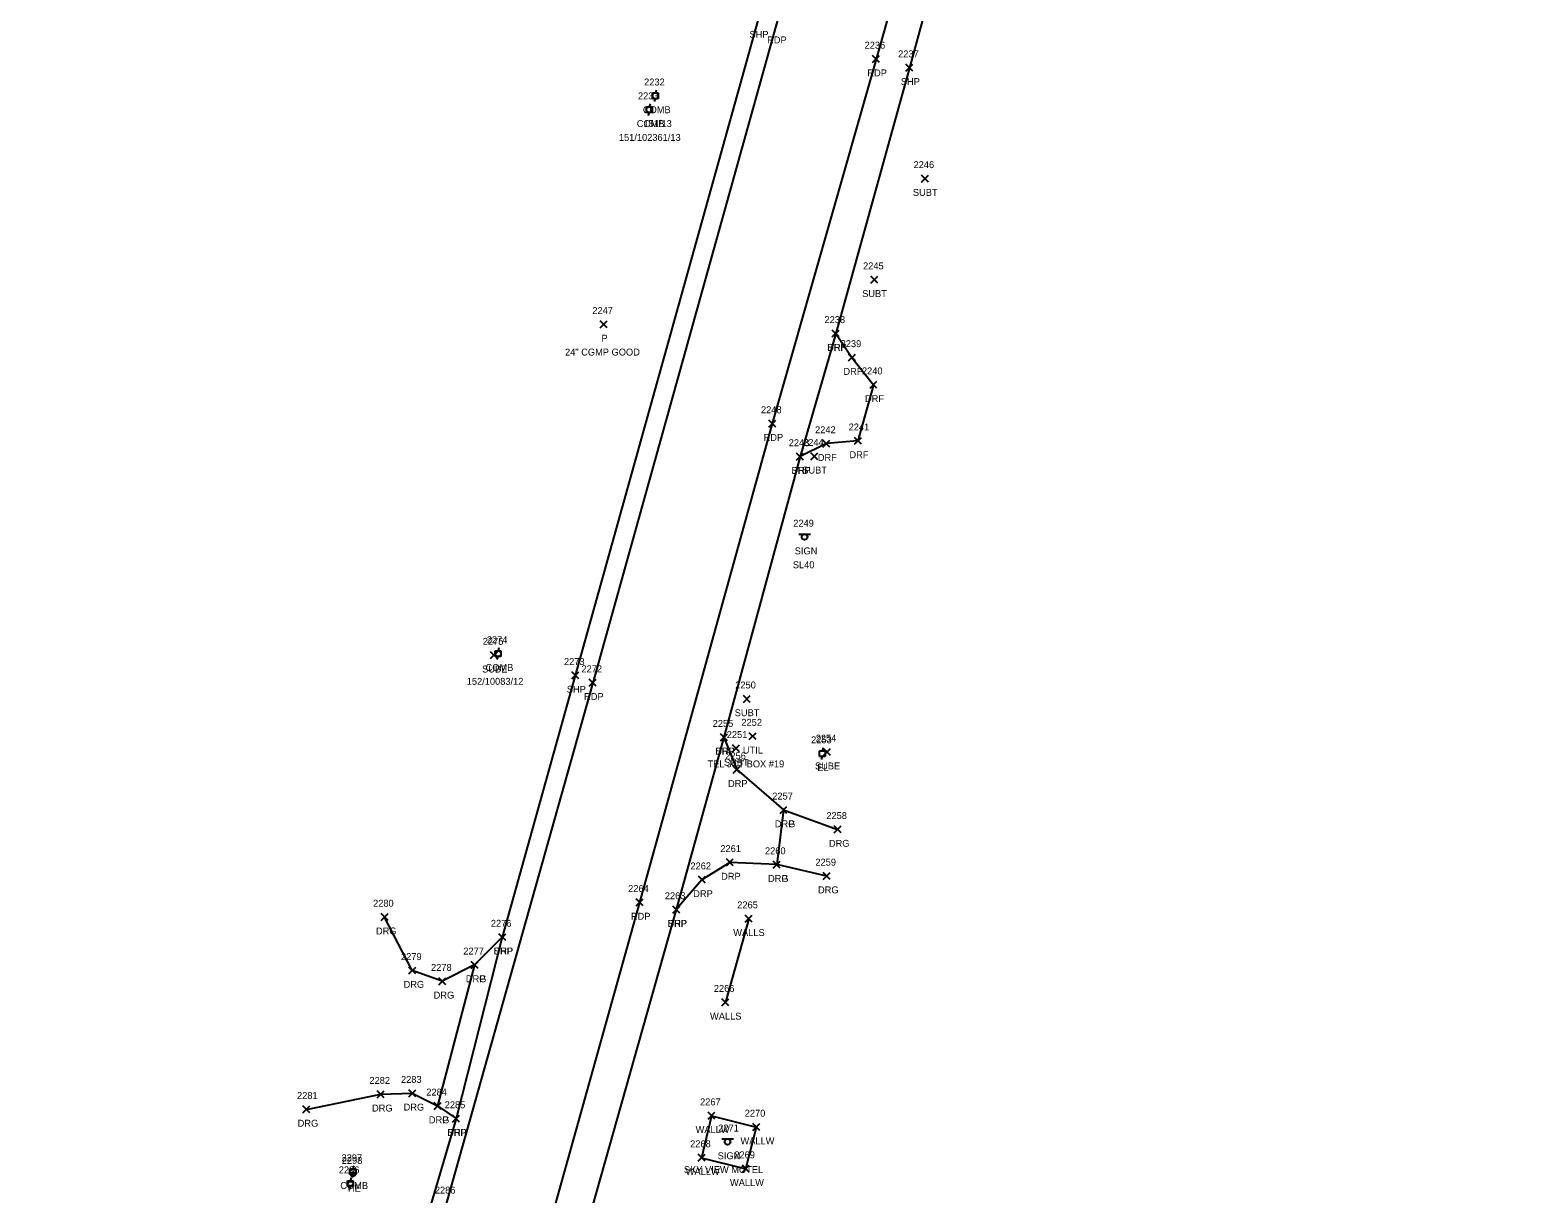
# Model space of a CAD drawing. Extents: x 1443071 to 1445292, y 614024 to 622563.
# Drawn here: x 1444319.1 to 1444754.4, y 621556.7 to 621892.6 of the extents above; entities that cross this region are included whole.
import ezdxf

# ---------------------------------------------------------------- set-up
doc = ezdxf.new("R2010")
doc.units = 0
for name, color, linetype in [('C_A', 7, 'Continuous'), ('C_I', 7, 'Continuous'), ('CBP', 7, 'Continuous'), ('D_A', 7, 'Continuous'), ('D_C', 7, 'Continuous'), ('D_I', 7, 'Continuous'), ('D_TIC', 7, 'Continuous'), ('L_A', 7, 'Continuous'), ('L_I', 7, 'Continuous'), ('L_TIC', 7, 'Continuous'), ('LW', 7, 'Continuous'), ('LWS', 7, 'Continuous'), ('P_A', 7, 'Continuous'), ('P_I', 7, 'Continuous'), ('P_TIC', 7, 'Continuous'), ('PET', 7, 'Continuous'), ('PSP', 7, 'Continuous'), ('R_A', 7, 'Continuous'), ('R_I', 7, 'Continuous'), ('R_TIC', 7, 'Continuous'), ('RDF', 7, 'Continuous'), ('RDG', 7, 'Continuous'), ('RDP', 7, 'Continuous'), ('S_A', 7, 'Continuous'), ('S_C', 7, 'Continuous'), ('S_I', 7, 'Continuous'), ('SSGN', 7, 'Continuous'), ('U_A', 7, 'Continuous'), ('U_C', 7, 'Continuous'), ('U_I', 7, 'Continuous'), ('U_TIC', 7, 'Continuous'), ('UDEFAULT', 7, 'Continuous'), ('UEPT', 7, 'Continuous'), ('UP', 7, 'Continuous')]:
    doc.layers.add(name, color=color, linetype=linetype)

msp = doc.modelspace()

# ---------------------------------------------------------------- linework, layer by layer
at = {"layer": 'CBP'}
for radius in [0.625, 0.0833]:
    msp.add_circle((1444412.36, 621562.38), radius, dxfattribs=at)
at = {"layer": 'D_TIC'}
for points in [[(1444483.71, 621806.69), (1444485.71, 621808.69)], [(1444485.71, 621806.69), (1444483.71, 621808.69)]]:
    msp.add_lwpolyline(points, dxfattribs=at)
at = {"layer": 'L_TIC'}
for points in [[(1444525.6, 621635.14), (1444527.6, 621637.14)], [(1444527.6, 621635.14), (1444525.6, 621637.14)], [(1444518.88, 621611.03), (1444520.88, 621613.03)], [(1444520.88, 621611.03), (1444518.88, 621613.03)], [(1444514.86, 621578.28), (1444516.86, 621580.28)], [(1444516.86, 621578.28), (1444514.86, 621580.28)], [(1444514.86, 621578.28), (1444516.86, 621580.28)], [(1444516.86, 621578.28), (1444514.86, 621580.28)], [(1444527.8, 621575.01), (1444529.8, 621577.01)], [(1444529.8, 621575.01), (1444527.8, 621577.01)], [(1444527.8, 621575.01), (1444529.8, 621577.01)], [(1444529.8, 621575.01), (1444527.8, 621577.01)], [(1444512, 621566.17), (1444514, 621568.17)], [(1444514, 621566.17), (1444512, 621568.17)], [(1444524.76, 621563), (1444526.76, 621565)], [(1444526.76, 621563), (1444524.76, 621565)]]:
    msp.add_lwpolyline(points, dxfattribs=at)
at = {"layer": 'LW'}
for points in [[(1444515.86, 621579.28), (1444513, 621567.17), (1444525.76, 621564), (1444528.8, 621576.01)], [(1444515.86, 621579.28), (1444528.8, 621576.01)]]:
    msp.add_lwpolyline(points, dxfattribs=at)
at = {"layer": 'LWS'}
msp.add_lwpolyline([(1444526.6, 621636.14), (1444519.88, 621612.03)], dxfattribs=at)
at = {"layer": 'P_TIC'}
for points in [[(1444562.37, 621883.27), (1444564.37, 621885.27)], [(1444564.37, 621883.27), (1444562.37, 621885.27)], [(1444571.99, 621880.76), (1444573.99, 621882.76)], [(1444573.99, 621880.76), (1444571.99, 621882.76)], [(1444550.74, 621804.05), (1444552.74, 621806.05)], [(1444552.74, 621804.05), (1444550.74, 621806.05)], [(1444532.4, 621778.05), (1444534.4, 621780.05)], [(1444534.4, 621778.05), (1444532.4, 621780.05)], [(1444540.41, 621768.53), (1444542.41, 621770.53)], [(1444542.41, 621768.53), (1444540.41, 621770.53)], [(1444475.53, 621705.36), (1444477.53, 621707.36)], [(1444477.53, 621705.36), (1444475.53, 621707.36)], [(1444480.57, 621703.27), (1444482.57, 621705.27)], [(1444482.57, 621703.27), (1444480.57, 621705.27)], [(1444518.46, 621687.51), (1444520.46, 621689.51)], [(1444520.46, 621687.51), (1444518.46, 621689.51)], [(1444494.09, 621639.86), (1444496.09, 621641.86)], [(1444496.09, 621639.86), (1444494.09, 621641.86)], [(1444504.68, 621637.77), (1444506.68, 621639.77)], [(1444506.68, 621637.77), (1444504.68, 621639.77)], [(1444454.46, 621629.82), (1444456.46, 621631.82)], [(1444456.46, 621629.82), (1444454.46, 621631.82)], [(1444441.09, 621577.45), (1444443.09, 621579.45)], [(1444443.09, 621577.45), (1444441.09, 621579.45)]]:
    msp.add_lwpolyline(points, dxfattribs=at)
at = {"layer": 'PET'}
for points in [[(1444754.44, 622544.13), (1444741.07, 622497.37), (1444724.21, 622436.63), (1444710.62, 622388.87), (1444697.45, 622342.15), (1444675, 622264.13), (1444650.85, 622183.92), (1444630.28, 622116), (1444610.88, 622049.25), (1444594.96, 621996.24), (1444563.37, 621884.27), (1444533.4, 621779.05), (1444495.09, 621640.86), (1444437.04, 621433.18), (1444409.83, 621332.84), (1444393.99, 621275.61), (1444360.23, 621155.32)], [(1444707.59, 622509.11), (1444700.19, 622484.07), (1444679.05, 622409.28), (1444655.77, 622327.83), (1444650.07, 622306.66), (1444636.13, 622255.68), (1444623.55, 622208.8), (1444606.26, 622146.53), (1444595.29, 622106.04), (1444582.56, 622060.23), (1444534.43, 621893.79), (1444481.57, 621704.27), (1444439.29, 621553.82), (1444408.11, 621445.28), (1444395.03, 621397.39), (1444367.96, 621301.44), (1444350.41, 621238.76), (1444319.14, 621126.97)]]:
    msp.add_lwpolyline(points, dxfattribs=at)
at = {"layer": 'PSP'}
for points in [[(1444703.05, 622509.58), (1444696.35, 622485.04), (1444679.96, 622426.95), (1444670.67, 622398.4), (1444651.65, 622328.99), (1444645.77, 622309.01), (1444600.31, 622147.99), (1444589.19, 622108.06), (1444575.49, 622063.15), (1444529.28, 621895.39), (1444476.53, 621706.36), (1444455.46, 621630.82), (1444442.09, 621578.45), (1444424.77, 621519.75), (1444412.09, 621475.26), (1444390.88, 621397.93), (1444363.76, 621301.82), (1444345.99, 621239.2), (1444324.65, 621163.68)], [(1444745.15, 622495.54), (1444738.65, 622472.69), (1444728.21, 622436.2), (1444714.89, 622387.13), (1444701.45, 622339.69), (1444679.77, 622260.17), (1444671.12, 622229.57), (1444657.52, 622182.26), (1444644.19, 622133.53), (1444626.95, 622072.43), (1444608.5, 622007.83), (1444599.1, 621977.5), (1444572.99, 621881.76), (1444551.74, 621805.05), (1444541.41, 621769.53), (1444519.46, 621688.51), (1444505.68, 621638.77), (1444452.32, 621450.13), (1444441.68, 621411.27), (1444418.22, 621330.76), (1444405.98, 621283.95), (1444397.04, 621252.99), (1444383.69, 621203.04)]]:
    msp.add_lwpolyline(points, dxfattribs=at)
at = {"layer": 'R_TIC'}
for points in [[(1444550.74, 621804.05), (1444552.74, 621806.05)], [(1444552.74, 621804.05), (1444550.74, 621806.05)], [(1444555.41, 621797.12), (1444557.41, 621799.12)], [(1444557.41, 621797.12), (1444555.41, 621799.12)], [(1444561.63, 621789.25), (1444563.63, 621791.25)], [(1444563.63, 621789.25), (1444561.63, 621791.25)], [(1444548.01, 621772.27), (1444550.01, 621774.27)], [(1444550.01, 621772.27), (1444548.01, 621774.27)], [(1444557.14, 621773.07), (1444559.14, 621775.07)], [(1444559.14, 621773.07), (1444557.14, 621775.07)], [(1444540.41, 621768.53), (1444542.41, 621770.53)], [(1444542.41, 621768.53), (1444540.41, 621770.53)], [(1444518.46, 621687.51), (1444520.46, 621689.51)], [(1444520.46, 621687.51), (1444518.46, 621689.51)], [(1444522.14, 621678.17), (1444524.14, 621680.17)], [(1444524.14, 621678.17), (1444522.14, 621680.17)], [(1444535.65, 621666.54), (1444537.65, 621668.54)], [(1444537.65, 621666.54), (1444535.65, 621668.54)], [(1444535.65, 621666.54), (1444537.65, 621668.54)], [(1444537.65, 621666.54), (1444535.65, 621668.54)], [(1444551.27, 621660.91), (1444553.27, 621662.91)], [(1444553.27, 621660.91), (1444551.27, 621662.91)], [(1444520.15, 621651.39), (1444522.15, 621653.39)], [(1444522.15, 621651.39), (1444520.15, 621653.39)], [(1444533.69, 621650.75), (1444535.69, 621652.75)], [(1444535.69, 621650.75), (1444533.69, 621652.75)], [(1444533.69, 621650.75), (1444535.69, 621652.75)], [(1444535.69, 621650.75), (1444533.69, 621652.75)], [(1444512.08, 621646.38), (1444514.08, 621648.38)], [(1444514.08, 621646.38), (1444512.08, 621648.38)], [(1444548.11, 621647.47), (1444550.11, 621649.47)], [(1444550.11, 621647.47), (1444548.11, 621649.47)], [(1444420.49, 621635.61), (1444422.49, 621637.61)], [(1444422.49, 621635.61), (1444420.49, 621637.61)], [(1444504.68, 621637.77), (1444506.68, 621639.77)], [(1444506.68, 621637.77), (1444504.68, 621639.77)], [(1444454.46, 621629.82), (1444456.46, 621631.82)], [(1444456.46, 621629.82), (1444454.46, 621631.82)], [(1444428.47, 621620.21), (1444430.47, 621622.21)], [(1444430.47, 621620.21), (1444428.47, 621622.21)], [(1444446.45, 621621.81), (1444448.45, 621623.81)], [(1444448.45, 621621.81), (1444446.45, 621623.81)], [(1444446.45, 621621.81), (1444448.45, 621623.81)], [(1444448.45, 621621.81), (1444446.45, 621623.81)], [(1444437.14, 621617.09), (1444439.14, 621619.09)], [(1444439.14, 621617.09), (1444437.14, 621619.09)], [(1444419.35, 621584.49), (1444421.35, 621586.49)], [(1444421.35, 621584.49), (1444419.35, 621586.49)], [(1444428.47, 621584.77), (1444430.47, 621586.77)], [(1444430.47, 621584.77), (1444428.47, 621586.77)], [(1444397.88, 621580.12), (1444399.88, 621582.12)], [(1444399.88, 621580.12), (1444397.88, 621582.12)], [(1444435.77, 621581.1), (1444437.77, 621583.1)], [(1444437.77, 621581.1), (1444435.77, 621583.1)], [(1444435.77, 621581.1), (1444437.77, 621583.1)], [(1444437.77, 621581.1), (1444435.77, 621583.1)], [(1444441.09, 621577.45), (1444443.09, 621579.45)], [(1444443.09, 621577.45), (1444441.09, 621579.45)]]:
    msp.add_lwpolyline(points, dxfattribs=at)
at = {"layer": 'RDF'}
msp.add_lwpolyline([(1444551.74, 621805.05), (1444556.41, 621798.12), (1444562.63, 621790.25), (1444558.14, 621774.07), (1444549.01, 621773.27), (1444541.41, 621769.53)], dxfattribs=at)
at = {"layer": 'RDG'}
for points in [[(1444536.65, 621667.54), (1444552.27, 621661.91)], [(1444549.11, 621648.47), (1444534.69, 621651.75)], [(1444447.45, 621622.81), (1444438.14, 621618.09), (1444429.47, 621621.21), (1444421.49, 621636.61)], [(1444398.88, 621581.12), (1444420.35, 621585.49), (1444429.47, 621585.77), (1444436.77, 621582.1)]]:
    msp.add_lwpolyline(points, dxfattribs=at)
at = {"layer": 'RDP'}
for points in [[(1444519.46, 621688.51), (1444523.14, 621679.17), (1444536.65, 621667.54), (1444534.69, 621651.75), (1444521.15, 621652.39), (1444513.08, 621647.38), (1444505.68, 621638.77)], [(1444455.46, 621630.82), (1444447.45, 621622.81), (1444436.77, 621582.1), (1444442.09, 621578.45)]]:
    msp.add_lwpolyline(points, dxfattribs=at)
at = {"layer": 'SSGN'}
for p, q in [((1444541.09, 621747.16), (1444544.43, 621747.16)), ((1444542.74, 621746.32), (1444542.74, 621746.32)), ((1444518.86, 621572.58), (1444522.19, 621572.58)), ((1444520.51, 621571.75), (1444520.51, 621571.75))]:
    msp.add_line(p, q, dxfattribs=at)
for centre in [(1444542.74, 621746.32), (1444520.51, 621571.75)]:
    msp.add_circle(centre, 0.833, dxfattribs=at)
at = {"layer": 'U_TIC'}
for points in [[(1444576.51, 621848.78), (1444578.51, 621850.78)], [(1444578.51, 621848.78), (1444576.51, 621850.78)], [(1444561.87, 621819.57), (1444563.87, 621821.57)], [(1444563.87, 621819.57), (1444561.87, 621821.57)], [(1444544.57, 621768.63), (1444546.57, 621770.63)], [(1444546.57, 621768.63), (1444544.57, 621770.63)], [(1444452.08, 621711.21), (1444454.08, 621713.21)], [(1444454.08, 621711.21), (1444452.08, 621713.21)], [(1444525.06, 621698.6), (1444527.06, 621700.6)], [(1444527.06, 621698.6), (1444525.06, 621700.6)], [(1444521.95, 621684.29), (1444523.95, 621686.29)], [(1444523.95, 621684.29), (1444521.95, 621686.29)], [(1444548.2, 621683.24), (1444550.2, 621685.24)], [(1444550.2, 621683.24), (1444548.2, 621685.24)]]:
    msp.add_lwpolyline(points, dxfattribs=at)
at = {"layer": 'UDEFAULT'}
for points in [[(1444526.74, 621687.83), (1444528.74, 621689.83)], [(1444528.74, 621687.83), (1444526.74, 621689.83)]]:
    msp.add_lwpolyline(points, dxfattribs=at)
at = {"layer": 'UEPT'}
for p, q in [((1444548.04, 621685.45), (1444547.87, 621684.62)), ((1444547.04, 621682.95), (1444547.04, 621684.62)), ((1444547.04, 621684.62), (1444548.71, 621684.62)), ((1444548.71, 621682.95), (1444547.04, 621682.95)), ((1444547.62, 621682.12), (1444547.87, 621682.95)), ((1444547.87, 621683.79), (1444547.87, 621683.79)), ((1444548.71, 621684.62), (1444548.71, 621682.95))]:
    msp.add_line(p, q, dxfattribs=at)
at = {"layer": 'UP'}
for p, q in [((1444498.82, 621872.81), (1444498.82, 621874.48)), ((1444498.82, 621874.48), (1444500.49, 621874.48)), ((1444500.49, 621872.81), (1444498.82, 621872.81)), ((1444499.4, 621871.98), (1444499.65, 621872.81)), ((1444499.9, 621875.31), (1444499.65, 621874.48)), ((1444499.65, 621873.64), (1444499.65, 621873.64)), ((1444500.49, 621874.48), (1444500.49, 621872.81)), ((1444497.06, 621868.8), (1444497.06, 621870.47)), ((1444497.06, 621870.47), (1444498.73, 621870.47)), ((1444498.73, 621868.8), (1444497.06, 621868.8)), ((1444497.64, 621867.97), (1444497.89, 621868.8)), ((1444498.14, 621871.3), (1444497.89, 621870.47)), ((1444497.89, 621869.64), (1444497.89, 621869.64)), ((1444498.73, 621870.47), (1444498.73, 621868.8)), ((1444453.41, 621711.82), (1444453.41, 621713.49)), ((1444453.41, 621713.49), (1444455.08, 621713.49)), ((1444455.08, 621711.82), (1444453.41, 621711.82)), ((1444453.99, 621710.99), (1444454.24, 621711.82)), ((1444454.49, 621714.32), (1444454.24, 621713.49)), ((1444454.24, 621712.66), (1444454.24, 621712.66)), ((1444455.08, 621713.49), (1444455.08, 621711.82)), ((1444411.46, 621562.31), (1444411.46, 621563.98)), ((1444411.46, 621563.98), (1444413.13, 621563.98)), ((1444412.55, 621564.81), (1444412.3, 621563.98)), ((1444412.3, 621563.15), (1444412.3, 621563.15)), ((1444413.13, 621563.98), (1444413.13, 621562.31)), ((1444410.73, 621558.82), (1444410.73, 621560.49)), ((1444410.73, 621560.49), (1444412.4, 621560.49)), ((1444412.4, 621558.82), (1444410.73, 621558.82)), ((1444411.31, 621557.99), (1444411.56, 621558.82)), ((1444413.13, 621562.31), (1444411.46, 621562.31)), ((1444411.81, 621561.32), (1444411.56, 621560.49)), ((1444411.56, 621559.66), (1444411.56, 621559.66)), ((1444412.05, 621561.48), (1444412.3, 621562.31)), ((1444412.4, 621560.49), (1444412.4, 621558.82))]:
    msp.add_line(p, q, dxfattribs=at)
for centre in [(1444499.65, 621873.64), (1444497.89, 621869.64), (1444454.24, 621712.66), (1444412.3, 621563.15), (1444411.56, 621559.66)]:
    msp.add_circle(centre, 0.833, dxfattribs=at)

# ---------------------------------------------------------------- texts
at = {"layer": 'C_A'}
msp.add_text('TIE', height=2, dxfattribs=at).set_placement((1444410.44, 621557.38))
at = {"layer": 'C_I'}
msp.add_text('2298', height=2, dxfattribs=at).set_placement((1444409.1, 621565.38))
at = {"layer": 'D_A'}
msp.add_text('P', height=2, dxfattribs=at).set_placement((1444484.09, 621802.69))
at = {"layer": 'D_C'}
msp.add_text('24" CGMP GOOD', height=2, dxfattribs=at).set_placement((1444473.57, 621798.69))
at = {"layer": 'D_I'}
msp.add_text('2247', height=2, dxfattribs=at).set_placement((1444481.45, 621810.69))
at = {"layer": 'L_A'}
for s, p in [('WALLS', (1444522.14, 621631.14)), ('WALLS', (1444515.43, 621607.03)), ('WALLW', (1444511.27, 621574.28)), ('WALLW', (1444511.27, 621574.28)), ('WALLW', (1444524.22, 621571.01)), ('WALLW', (1444524.22, 621571.01)), ('WALLW', (1444508.42, 621562.17)), ('WALLW', (1444521.18, 621559))]:
    msp.add_text(s, height=2, dxfattribs=at).set_placement(p)
at = {"layer": 'L_I'}
for s, p in [('2265', (1444523.29, 621639.14)), ('2266', (1444516.52, 621615.03)), ('2267', (1444512.55, 621582.28)), ('2267', (1444512.55, 621582.28)), ('2270', (1444525.45, 621579.01)), ('2270', (1444525.45, 621579.01)), ('2268', (1444509.69, 621570.17)), ('2269', (1444522.45, 621567))]:
    msp.add_text(s, height=2, dxfattribs=at).set_placement(p)
at = {"layer": 'P_A'}
for s, p in [('SHP', (1444526.81, 621890.39)), ('RDP', (1444531.92, 621888.79)), ('RDP', (1444560.86, 621879.27)), ('SHP', (1444570.53, 621876.76)), ('SHP', (1444549.28, 621800.05)), ('RDP', (1444530.89, 621774.05)), ('SHP', (1444538.94, 621764.53)), ('SHP', (1444474.07, 621701.36)), ('RDP', (1444479.06, 621699.27)), ('SHP', (1444516.99, 621683.51)), ('RDP', (1444492.58, 621635.86)), ('SHP', (1444503.22, 621633.77)), ('SHP', (1444453, 621625.82)), ('SHP', (1444439.62, 621573.45))]:
    msp.add_text(s, height=2, dxfattribs=at).set_placement(p)
at = {"layer": 'P_I'}
for s, p in [('2236', (1444560.06, 621887.27)), ('2237', (1444569.73, 621884.76)), ('2238', (1444548.48, 621808.05)), ('2248', (1444530.14, 621782.05)), ('2243', (1444538.15, 621772.53)), ('2273', (1444473.27, 621709.36)), ('2272', (1444478.31, 621707.27)), ('2255', (1444516.2, 621691.51)), ('2264', (1444491.79, 621643.86)), ('2263', (1444502.38, 621641.77)), ('2276', (1444452.15, 621633.82)), ('2285', (1444438.83, 621581.45)), ('2286', (1444435.98, 621556.82))]:
    msp.add_text(s, height=2, dxfattribs=at).set_placement(p)
at = {"layer": 'R_A'}
for s, p in [('DRF', (1444549.28, 621800.05)), ('DRF', (1444553.95, 621793.12)), ('DRF', (1444560.17, 621785.25)), ('DRF', (1444546.55, 621768.27)), ('DRF', (1444555.68, 621769.07)), ('DRF', (1444538.94, 621764.53)), ('DRP', (1444516.95, 621683.51)), ('DRP', (1444520.62, 621674.17)), ('DRG', (1444534.14, 621662.54)), ('DRP', (1444534.14, 621662.54)), ('DRG', (1444549.76, 621656.91)), ('DRP', (1444518.64, 621647.39)), ('DRG', (1444532.18, 621646.75)), ('DRP', (1444532.18, 621646.75)), ('DRP', (1444510.57, 621642.38)), ('DRG', (1444546.6, 621643.47)), ('DRG', (1444418.97, 621631.61)), ('DRP', (1444503.17, 621633.77)), ('DRP', (1444452.95, 621625.82)), ('DRG', (1444444.93, 621617.81)), ('DRP', (1444444.93, 621617.81)), ('DRG', (1444426.96, 621616.21)), ('DRG', (1444435.63, 621613.09)), ('DRG', (1444417.84, 621580.49)), ('DRG', (1444426.96, 621580.77)), ('DRG', (1444396.37, 621576.12)), ('DRG', (1444434.25, 621577.1)), ('DRP', (1444434.25, 621577.1)), ('DRP', (1444439.57, 621573.45))]:
    msp.add_text(s, height=2, dxfattribs=at).set_placement(p)
at = {"layer": 'R_I'}
for s, p in [('2238', (1444548.48, 621808.05)), ('2239', (1444553.14, 621801.12)), ('2240', (1444559.29, 621793.25)), ('2242', (1444545.75, 621776.27)), ('2241', (1444555.45, 621777.07)), ('2243', (1444538.15, 621772.53)), ('2255', (1444516.2, 621691.51)), ('2256', (1444519.82, 621682.17)), ('2257', (1444533.39, 621670.54)), ('2257', (1444533.39, 621670.54)), ('2258', (1444549.01, 621664.91)), ('2261', (1444518.41, 621655.39)), ('2260', (1444531.3, 621654.75)), ('2260', (1444531.3, 621654.75)), ('2262', (1444509.77, 621650.38)), ('2259', (1444545.85, 621651.47)), ('2280', (1444418.14, 621639.61)), ('2263', (1444502.38, 621641.77)), ('2276', (1444452.15, 621633.82)), ('2279', (1444426.21, 621624.21)), ('2277', (1444444.19, 621625.81)), ('2277', (1444444.19, 621625.81)), ('2278', (1444434.88, 621621.09)), ('2282', (1444417.09, 621588.49)), ('2283', (1444426.21, 621588.77)), ('2281', (1444396.19, 621584.12)), ('2284', (1444433.51, 621585.1)), ('2284', (1444433.51, 621585.1)), ('2285', (1444438.83, 621581.45))]:
    msp.add_text(s, height=2, dxfattribs=at).set_placement(p)
at = {"layer": 'S_A'}
for p in [(1444539.88, 621741.3), (1444517.65, 621566.73)]:
    msp.add_text('SIGN', height=2, dxfattribs=at).set_placement(p)
at = {"layer": 'S_C'}
for s, p in [('SL40', (1444539.33, 621737.3)), ('SKY VIEW MOTEL', (1444507.89, 621562.73))]:
    msp.add_text(s, height=2, dxfattribs=at).set_placement(p)
at = {"layer": 'S_I'}
for s, p in [('2249', (1444539.45, 621749.3)), ('2271', (1444517.8, 621574.73))]:
    msp.add_text(s, height=2, dxfattribs=at).set_placement(p)
at = {"layer": 'U_A'}
for s, p in [('COMB', (1444496.04, 621868.64)), ('COMB', (1444494.28, 621864.64)), ('SUBT', (1444574, 621844.78)), ('SUBT', (1444559.36, 621815.57)), ('SUBT', (1444542.06, 621764.63)), ('SUBE', (1444449.62, 621707.21)), ('COMB', (1444450.63, 621707.66)), ('SUBT', (1444522.56, 621694.6)), ('UTIL', (1444524.9, 621683.83)), ('SUBT', (1444519.45, 621680.29)), ('SUBE', (1444545.73, 621679.24)), ('EL', (1444546.41, 621678.79)), ('COMB', (1444408.68, 621558.15))]:
    msp.add_text(s, height=2, dxfattribs=at).set_placement(p)
at = {"layer": 'U_C'}
for s, p in [('151/13', (1444496.22, 621864.64)), ('151/102361/13', (1444489.11, 621860.64)), ('152/10083/12', (1444445.19, 621703.66)), ('TEL JCT BOX #19', (1444514.71, 621679.83))]:
    msp.add_text(s, height=2, dxfattribs=at).set_placement(p)
at = {"layer": 'U_I'}
for s, p in [('2232', (1444496.39, 621876.64)), ('2233', (1444494.63, 621872.64)), ('2246', (1444574.19, 621852.78)), ('2245', (1444559.61, 621823.57)), ('2244', (1444542.31, 621772.63)), ('2275', (1444449.82, 621715.21)), ('2274', (1444450.98, 621715.66)), ('2250', (1444522.71, 621702.6)), ('2252', (1444524.48, 621691.83)), ('2251', (1444520.26, 621688.29)), ('2254', (1444545.94, 621687.24)), ('2253', (1444544.61, 621686.79)), ('2297', (1444409.04, 621566.15)), ('2296', (1444408.25, 621562.66))]:
    msp.add_text(s, height=2, dxfattribs=at).set_placement(p)

doc.saveas('drawing.dxf')
